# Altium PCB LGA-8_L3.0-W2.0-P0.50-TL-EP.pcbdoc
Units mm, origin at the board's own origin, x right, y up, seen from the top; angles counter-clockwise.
Board outline 15.9 x 15.3 mm, 2 copper layers (Top Layer, Bottom Layer), stack 0 mm thick; 1 components, 0 nets, 9 pads, 0 vias.
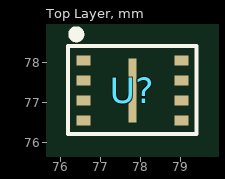
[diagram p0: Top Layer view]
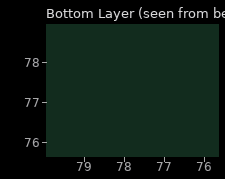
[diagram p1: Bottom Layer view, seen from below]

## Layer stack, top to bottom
Top Layer: signal copper (thickness not stored)
Bottom Layer: signal copper (thickness not stored)

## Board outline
85.75,69.85 69.85,69.85 69.85,85.149 85.75,85.149

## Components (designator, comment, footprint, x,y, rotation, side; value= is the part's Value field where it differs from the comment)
U? "" LGA-8_L3.0-W2.0-P0.50-TL-EP 77.801,77.299 r0 top

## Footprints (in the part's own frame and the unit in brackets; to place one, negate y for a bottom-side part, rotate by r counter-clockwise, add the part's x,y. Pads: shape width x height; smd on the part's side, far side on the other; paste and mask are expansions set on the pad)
LGA-8_L3.0-W2.0-P0.50-TL-EP [mm]
  rect 0.35x0.25 smd: 1(-1.225,0.75) 2(-1.225,0.25) 3(-1.225,-0.25) 4(-1.225,-0.75) 5(1.225,-0.75) 6(1.225,-0.25) 7(1.225,0.25) 8(1.225,0.75)
  rect 0.2x1.6 smd: 9(0,0)
  silkscreen extent -1.6,-1.1 1.6,1.5

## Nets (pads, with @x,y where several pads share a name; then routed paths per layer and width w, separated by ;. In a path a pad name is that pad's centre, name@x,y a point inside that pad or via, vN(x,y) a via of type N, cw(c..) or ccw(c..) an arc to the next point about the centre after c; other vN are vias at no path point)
pads on no net: U?.1 U?.2 U?.3 U?.4 U?.5 U?.6 U?.7 U?.8 U?.9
